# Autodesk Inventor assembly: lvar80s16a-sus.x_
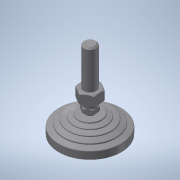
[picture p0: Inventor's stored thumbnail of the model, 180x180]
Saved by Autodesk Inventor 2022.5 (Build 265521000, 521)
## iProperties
Part Number: lvar80s16a-sus.x_
Material: 一般
Document SubType Name: Assembly
Designer: ImaoCorp
Sending System: SOLIDWORKS 2017-2017317
MC: AMD64
MC_MODEL: Intel64 Family 6 Model 60 Stepping 3, GenuineIntel
OS: Windows_NT
FRU: Parasolid Version 29.0, build 201,  4-17-2017
FORMAT: text
GUISE: transmit
KEY: lvar80s16a-sus
FILE: lvar80s16a-sus.x_t
DATE: Mon Jul 01 18:16:04 2019
Author: ImaoCorp
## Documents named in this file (3)
- X:\14_SW2022-Inv2022\00_全2023-1023新製品(TCC)まで\l\lvar80s16a-sus\LVAR80S16A-SUS.iam
- X:\14_SW2022-Inv2022\00_全2023-1023新製品(TCC)まで\l\lvar80s16a-sus\lvar80s16a-sus_01.ipt
- X:\14_SW2022-Inv2022\00_全2023-1023新製品(TCC)まで\l\lvar80s16a-sus\lvar80s16a-sus_02.ipt
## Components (2 placed, 2 different names)
1. lvar80s16a-sus_01
2. lvar80s16a-sus_02
